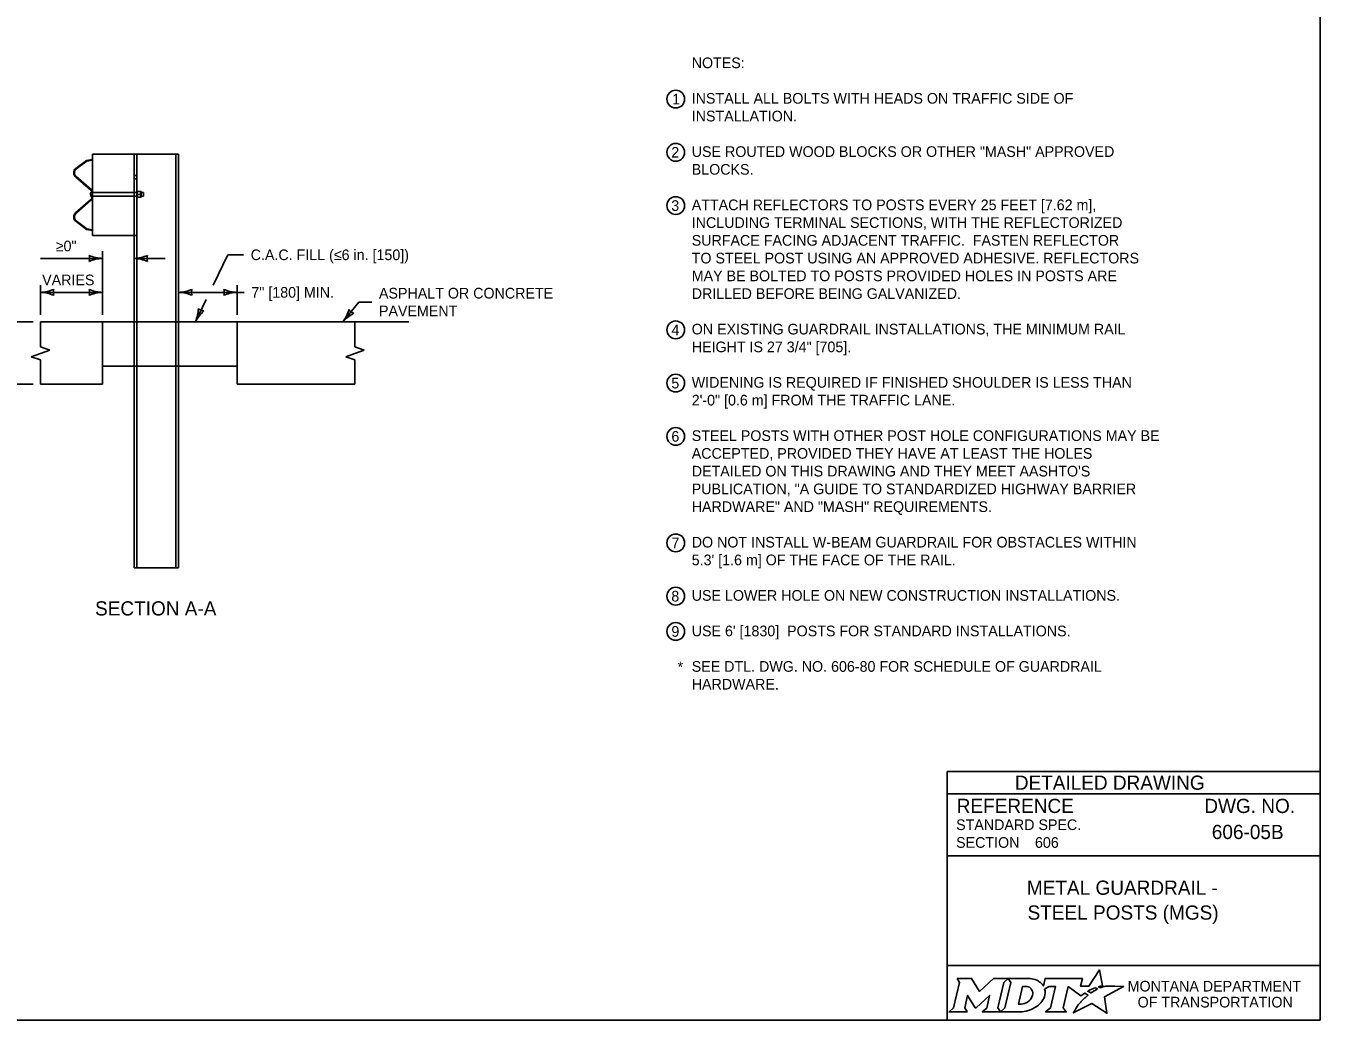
# Model space of a CAD drawing. Extents: x 49991.4 to 50021, y 49987.6 to 50011.4.
# Drawn here: x 50009.46 to 50016.75, y 49987.8 to 49993.4 of the extents above; entities that cross this region are included whole.
import ezdxf

# ---------------------------------------------------------------- set-up
doc = ezdxf.new("R2010")
doc.units = 0
for name, color, linetype in [('Default', 7, 'Continuous'), ('Level 1', 7, 'Continuous'), ('Level 2', 7, 'Continuous'), ('Level 3', 7, 'Continuous'), ('Level 4', 7, 'Continuous'), ('Level 5', 7, 'Continuous'), ('Level 6', 7, 'Continuous')]:
    doc.layers.add(name, color=color, linetype=linetype)

msp = doc.modelspace()

# ---------------------------------------------------------------- linework, layer by layer
at = {"layer": 'Default'}
for points in [[(50014.7056, 49988.0338), (50014.7197, 49988.0104), (50014.6862, 49987.8671), (50014.6605, 49987.8446), (50014.7621, 49987.8446), (50014.7486, 49987.8674), (50014.7648, 49987.9375), (50014.8085, 49987.8685), (50014.8138, 49987.8685), (50014.8889, 49987.938), (50014.8725, 49987.8669), (50014.8478, 49987.8449), (50014.9494, 49987.8449), (50014.9356, 49987.8682), (50014.9688, 49988.0106)], [(50014.9688, 49988.0106), (50014.9941, 49988.0338), (50014.9117, 49988.0338), (50014.8321, 49987.9608), (50014.7876, 49988.0335), (50014.7056, 49988.0338)], [(50015.1077, 49988.0338), (50014.9941, 49988.0338), (50015.0088, 49988.0109), (50014.9749, 49987.8671), (50014.9494, 49987.8449), (50015.06, 49987.8449)], [(50015.5126, 49987.9811), (50015.5023, 49987.9867), (50015.5139, 49987.9895), (50015.5255, 49987.9915), (50015.5081, 49988.0816), (50015.4486, 49987.9903), (50015.4013, 49987.9896), (50015.4116, 49988.0337), (50015.2024, 49988.0338), (50015.1923, 49987.9913), (50015.1865, 49987.9996)], [(50015.1317, 49987.9471), (50015.1305, 49987.939), (50015.1273, 49987.9297), (50015.1231, 49987.9215), (50015.1175, 49987.914), (50015.111, 49987.9071), (50015.1031, 49987.9008), (50015.0948, 49987.8961), (50015.0857, 49987.8922), (50015.0766, 49987.8899), (50015.0674, 49987.889), (50015.0515, 49987.889), (50015.0751, 49987.989), (50015.0911, 49987.989), (50015.0987, 49987.9884), (50015.1063, 49987.9865), (50015.1129, 49987.9835), (50015.119, 49987.9793), (50015.1238, 49987.9743), (50015.1275, 49987.9683), (50015.1302, 49987.9621), (50015.1318, 49987.9547), (50015.1318, 49987.9517), (50015.1317, 49987.9471)], [(50015.1991, 49987.9747), (50015.2237, 49987.9878), (50015.2606, 49987.9878), (50015.232, 49987.8673), (50015.2045, 49987.8446), (50015.3207, 49987.8446), (50015.3037, 49987.8675), (50015.3319, 49987.9877), (50015.4032, 49987.936), (50015.4243, 49987.9511), (50015.444, 49987.9402)], [(50015.3882, 49987.8843), (50015.3729, 49987.8599), (50015.3682, 49987.8524), (50015.3624, 49987.8438), (50015.3601, 49987.8395), (50015.4654, 49987.8926), (50015.5493, 49987.8375), (50015.5362, 49987.9302), (50015.6431, 49987.9886), (50015.5938, 49987.9894), (50015.5637, 49987.9898), (50015.5429, 49987.9901), (50015.5361, 49987.9886), (50015.5312, 49987.9874), (50015.5228, 49987.9851), (50015.5126, 49987.9811)], [(50015.4622, 49987.9535), (50015.4598, 49987.9518), (50015.4415, 49987.9614), (50015.4518, 49987.9671), (50015.4559, 49987.9693), (50015.4645, 49987.9733), (50015.4702, 49987.9759), (50015.4781, 49987.9789), (50015.4854, 49987.9816), (50015.4972, 49987.9742), (50015.4932, 49987.9721), (50015.4886, 49987.9696), (50015.4844, 49987.9674), (50015.4794, 49987.9645), (50015.4775, 49987.9634), (50015.4748, 49987.9618), (50015.4723, 49987.9604), (50015.47, 49987.9588), (50015.4674, 49987.957), (50015.4647, 49987.9552), (50015.4622, 49987.9535)], [(50015.1057, 49987.8522), (50015.1141, 49987.8548), (50015.1271, 49987.8602), (50015.1475, 49987.8712)], [(50015.4021, 49987.9004), (50015.4021, 49987.9004)]]:
    msp.add_lwpolyline(points, dxfattribs=at)
for centre, radius, start, end in [((50015.1308, 49987.9554), 0.0709, 339.53292, 15.85821), ((50015.0868, 49987.9727), 0.1183, 300.91025, 339.13831)]:
    msp.add_arc(centre, radius, start, end, dxfattribs=at)
for centre, major_axis, ratio, start_param, end_param in [((50015.1056, 49987.9864), (0.0834, -0.0037), 0.568097, 0.61298, 1.570796), ((50015.1612, 49987.9937), (0.0361, -0.0295), 0.469099, 1.225588, 1.570796), ((50015.4329, 49987.9305), (-0.0112, -0.0097), 0.021651, 3.157348, 6.283185), ((50015.3952, 49987.8923), (-0.00694, -0.00806), 0.008222, 0, 3.137361), ((50015.4119, 49987.9106), (-0.0098, -0.0102), 0.016458, 3.141593, 6.279097), ((50015.0603, 49987.9932), (0, 0.1484), 0.987302, 3.139398, 3.456847)]:
    msp.add_ellipse(centre, major_axis=major_axis, ratio=ratio, start_param=start_param, end_param=end_param, dxfattribs=at)
at = {"layer": 'Level 1'}
for p, q in [((50009.8373, 49992.6765), (50010.1496, 49992.6766)), ((50009.8373, 49992.2175), (50009.8373, 49992.6765)), ((50010.0874, 49992.6765), (50010.0874, 49991.7316)), ((50010.2433, 49992.6766), (50010.1496, 49992.6766)), ((50010.2433, 49992.6766), (50010.3216, 49992.6766)), ((50010.3057, 49992.6766), (50010.3057, 49991.7316)), ((50010.3216, 49992.6766), (50010.3216, 49991.7316)), ((50009.8033, 49992.6409), (50009.7436, 49992.5962)), ((50009.8049, 49992.6373), (50009.7459, 49992.5931)), ((50009.8373, 49992.647), (50009.8033, 49992.6409)), ((50009.8373, 49992.6429), (50009.8049, 49992.6373)), ((50009.7419, 49992.5484), (50009.827, 49992.4743)), ((50009.7444, 49992.5513), (50009.8295, 49992.4772)), ((50010.0874, 49992.4704), (50010.0893, 49992.4704)), ((50010.0893, 49992.4704), (50010.0893, 49992.4293)), ((50010.0894, 49992.4665), (50010.1109, 49992.4665)), ((50010.1109, 49992.4335), (50010.1109, 49992.4665)), ((50010.124, 49992.4596), (50010.1109, 49992.4596)), ((50010.124, 49992.4596), (50010.124, 49992.4402)), ((50009.7419, 49992.346), (50009.8267, 49992.4199)), ((50009.7444, 49992.3431), (50009.8309, 49992.4184)), ((50009.8354, 49992.4501), (50009.8256, 49992.4501)), ((50010.0874, 49992.4293), (50010.0893, 49992.4293)), ((50010.0893, 49992.4501), (50010.1109, 49992.4501)), ((50010.0894, 49992.4335), (50010.1109, 49992.4335)), ((50010.124, 49992.4402), (50010.1109, 49992.4402)), ((50009.8033, 49992.253), (50009.7436, 49992.2982)), ((50009.8049, 49992.2567), (50009.7459, 49992.3013)), ((50009.8373, 49992.247), (50009.8033, 49992.253)), ((50009.8373, 49992.251), (50009.8049, 49992.2567)), ((50009.8373, 49992.2175), (50010.0874, 49992.2175)), ((50010.0715, 49991.7316), (50010.0715, 49992.2175)), ((50009.5438, 49991.7316), (50010.0715, 49991.7316)), ((50009.8938, 49991.3816), (50009.8938, 49991.7316)), ((50010.3216, 49991.7316), (50011.6178, 49991.7316)), ((50010.652, 49991.7316), (50010.652, 49991.3816)), ((50010.0715, 49991.4829), (50009.8938, 49991.4829)), ((50010.3216, 49991.4829), (50010.652, 49991.4829)), ((50009.5438, 49991.3816), (50009.8938, 49991.3816)), ((50010.652, 49991.3816), (50011.3152, 49991.3816))]:
    msp.add_line(p, q, dxfattribs=at)
for points in [[(49999.3835, 49998.9992), (50016.7501, 49998.9992), (50016.7501, 49987.7988), (49999.3835, 49987.7988)], [(50009.8938, 49991.7316), (50010.652, 49991.7316), (50010.652, 49991.4829), (50009.8938, 49991.4829)]]:
    msp.add_lwpolyline(points, close=True, dxfattribs=at)
for centre, radius, start, end in [((50009.7621, 49992.5716), 0.0308, 126.89692, 228.93931), ((50009.7621, 49992.5716), 0.0269, 126.89692, 228.93931), ((50009.8068, 49992.4512), 0.0306, 5.90227, 48.93931), ((50009.8068, 49992.4512), 0.0345, 28.10432, 48.93931), ((50009.8068, 49992.4432), 0.0306, 310.4718, 354.09773), ((50009.8068, 49992.4432), 0.0345, 314.1015, 331.89568), ((50009.7621, 49992.3228), 0.0308, 131.06069, 233.10308), ((50009.7621, 49992.3228), 0.0269, 131.06069, 233.10308)]:
    msp.add_arc(centre, radius, start, end, dxfattribs=at)
for centre, major_axis, ratio, start_param, end_param in [((50009.8353, 49992.4498), (0, 0.0146), 0.663267, 0.091019, 3.253139), ((50010.1024, 49992.4583), (0.00829, 0.00104), 0.990733, 4.587776, 7.59993), ((50010.1024, 49992.4418), (-0.00829, -0.00104), 0.990733, 1.547621, 4.582997)]:
    msp.add_ellipse(centre, major_axis=major_axis, ratio=ratio, start_param=start_param, end_param=end_param, dxfattribs=at)
at = {"layer": 'Level 2'}
for centre in [(50013.1216, 49992.9868), (50013.1216, 49992.6868), (50013.1216, 49992.3868), (50013.1216, 49991.6868), (50013.1216, 49991.3868), (50013.1216, 49991.0868), (50013.1216, 49990.4868), (50013.1216, 49990.1868), (50013.1216, 49989.9882)]:
    msp.add_circle(centre, 0.05, dxfattribs=at)
at = {"layer": 'Level 3'}
for p, q in [((50009.8938, 49991.7716), (50009.8938, 49992.1293)), ((50010.5161, 49991.9381), (50010.5987, 49992.1096)), ((50010.5987, 49992.1096), (50010.6881, 49992.1096)), ((50009.5438, 49992.0893), (50009.8938, 49992.0893)), ((50010.0715, 49992.0893), (50010.2465, 49992.0893)), ((50009.5438, 49991.7716), (50009.5438, 49991.9381)), ((50009.5438, 49991.8981), (50009.8938, 49991.8981)), ((50010.3216, 49991.8981), (50010.4969, 49991.8981)), ((50010.4969, 49991.8981), (50010.692, 49991.8981)), ((50010.652, 49991.7716), (50010.652, 49991.9381)), ((50010.4168, 49991.7316), (50010.4776, 49991.8581)), ((50011.3365, 49991.8434), (50011.2475, 49991.7316)), ((50011.4104, 49991.8434), (50011.3365, 49991.8434)), ((50009.1538, 49991.7316), (50009.5038, 49991.7316)), ((50009.1538, 49991.3816), (50009.5038, 49991.3816))]:
    msp.add_line(p, q, dxfattribs=at)
for centre, radius, start, end in [((50009.903, 49992.3114), 0.2223, 247.45601, 267.63952), ((50009.7656, 49992.0893), 0.0548, 342.13882, 17.86118), ((50010.06, 49992.322), 0.233, 272.82731, 292.07716), ((50010.1997, 49992.0893), 0.0548, 162.13882, 197.86118), ((50009.9053, 49991.8566), 0.233, 92.82731, 112.07716), ((50010.0623, 49991.8671), 0.2223, 67.45601, 87.63952), ((50009.5323, 49992.1308), 0.233, 272.82731, 292.07716), ((50009.5347, 49991.676), 0.2223, 67.45601, 87.63952), ((50009.672, 49991.8981), 0.0548, 162.13882, 197.86118), ((50009.903, 49992.1202), 0.2223, 247.45601, 267.63952), ((50009.7656, 49991.8981), 0.0548, 342.13882, 17.86118), ((50009.9053, 49991.6654), 0.233, 92.82731, 112.07716), ((50010.3101, 49992.1308), 0.233, 272.82731, 292.07716), ((50010.3124, 49991.676), 0.2223, 67.45601, 87.63952), ((50010.4498, 49991.8981), 0.0548, 162.13882, 197.86118), ((50010.6612, 49992.1202), 0.2223, 247.45601, 267.63952), ((50010.5238, 49991.8981), 0.0548, 342.13882, 17.86118), ((50010.6635, 49991.6654), 0.233, 92.82731, 112.07716), ((50010.201, 49991.8196), 0.233, 337.82731, 357.07716), ((50010.471, 49991.8478), 0.0548, 227.13882, 262.86118), ((50011.0582, 49991.8676), 0.233, 324.30303, 343.55288), ((50011.3273, 49991.8319), 0.0548, 213.61454, 249.3369), ((50010.6142, 49991.6295), 0.2223, 132.45601, 152.63952), ((50011.4155, 49991.5861), 0.2223, 118.93173, 139.11524)]:
    msp.add_arc(centre, radius, start, end, dxfattribs=at)
at = {"layer": 'Level 4'}
for p, q in [((50010.0715, 49992.6765), (50010.0715, 49992.2175)), ((50010.0874, 49992.5568), (50010.0715, 49992.5568)), ((50010.0874, 49992.5374), (50010.0715, 49992.5374)), ((50010.0874, 49992.4596), (50009.8373, 49992.4596)), ((50010.0874, 49992.4402), (50009.8373, 49992.4402)), ((50010.0715, 49991.7316), (50010.0715, 49990.3468)), ((50010.0874, 49991.7316), (50010.0874, 49990.3468)), ((50010.3057, 49990.3468), (50010.3057, 49991.7316)), ((50010.3216, 49990.3468), (50010.3216, 49991.7316)), ((50010.0715, 49990.3468), (50010.3216, 49990.3468)), ((50014.6501, 49989.1988), (50014.6501, 49987.7988)), ((50016.7501, 49989.1988), (50014.6501, 49989.1988)), ((50016.7501, 49989.0738), (50014.6501, 49989.0738)), ((50016.7501, 49988.7238), (50014.6501, 49988.7238)), ((50016.7501, 49988.1057), (50014.6501, 49988.1057))]:
    msp.add_line(p, q, dxfattribs=at)
at = {"layer": 'Level 5'}
for p, q in [((50016.3862, 49988.8587), (50016.3862, 49988.8587)), ((50015.1444, 49988.7993), (50015.1444, 49988.7993)), ((50015.7001, 49988.4747), (50015.7001, 49988.4747))]:
    msp.add_line(p, q, dxfattribs=at)
at = {"layer": 'Level 6'}
for p, q in [((50009.5438, 49991.7316), (50009.5438, 49991.5913)), ((50011.3152, 49991.7316), (50011.3152, 49991.5913)), ((50009.5962, 49991.5728), (50009.5438, 49991.5913)), ((50011.3676, 49991.5728), (50011.3152, 49991.5913)), ((50009.5438, 49991.5542), (50009.4915, 49991.5357)), ((50009.5438, 49991.5171), (50009.4915, 49991.5357)), ((50009.5962, 49991.5728), (50009.5438, 49991.5542)), ((50009.5438, 49991.5171), (50009.5438, 49991.3816)), ((50011.3152, 49991.5542), (50011.2629, 49991.5357)), ((50011.3152, 49991.5171), (50011.2629, 49991.5357)), ((50011.3676, 49991.5728), (50011.3152, 49991.5542)), ((50011.3152, 49991.5171), (50011.3152, 49991.3816))]:
    msp.add_line(p, q, dxfattribs=at)

# ---------------------------------------------------------------- texts
at = {"layer": 'Default'}
for s, p in [('MONTANA DEPARTMENT', (50015.6663, 49987.96)), ('OF TRANSPORTATION', (50015.7225, 49987.87))]:
    msp.add_text(s, height=0.06, rotation=360, dxfattribs=at).set_placement(p)
at = {"layer": 'Level 2'}
for s, height, p in [('NOTES:', 0.06, (50013.2116, 49993.1609)), ('1', 0.06, (50013.1018, 49992.9568)), ('INSTALL ALL BOLTS WITH HEADS ON TRAFFIC SIDE OF ', 0.06, (50013.2116, 49992.9609)), ('INSTALLATION.', 0.06, (50013.2116, 49992.8609)), ('2', 0.06, (50013.0964, 49992.6568)), ('USE ROUTED WOOD BLOCKS OR OTHER "MASH" APPROVED ', 0.06, (50013.2116, 49992.6609)), ('BLOCKS.', 0.06, (50013.2116, 49992.5609)), ('3', 0.06, (50013.0964, 49992.3568)), ('ATTACH REFLECTORS TO POSTS EVERY 25 FEET [7.62 m], ', 0.06, (50013.2116, 49992.3609)), ('INCLUDING TERMINAL SECTIONS, WITH THE REFLECTORIZED ', 0.06, (50013.2116, 49992.2609)), ('≥0"', 0.06, (50009.6302, 49992.1293)), ('SURFACE FACING ADJACENT TRAFFIC.  FASTEN REFLECTOR ', 0.06, (50013.2116, 49992.1609)), ('C.A.C. FILL (≤6 in. [150])', 0.06, (50010.7281, 49992.0796)), ('TO STEEL POST USING AN APPROVED ADHESIVE. REFLECTORS ', 0.06, (50013.2116, 49992.0609)), ('MAY BE BOLTED TO POSTS PROVIDED HOLES IN POSTS ARE ', 0.06, (50013.2116, 49991.9609)), ('VARIES', 0.06, (50009.5538, 49991.9381)), ('7" [180] MIN.', 0.06, (50010.732, 49991.8681)), ('ASPHALT OR CONCRETE', 0.06, (50011.4504, 49991.8634)), ('DRILLED BEFORE BEING GALVANIZED.', 0.06, (50013.2116, 49991.8609)), ('PAVEMENT', 0.06, (50011.4504, 49991.7634)), ('4', 0.06, (50013.0976, 49991.6568)), ('ON EXISTING GUARDRAIL INSTALLATIONS, THE MINIMUM RAIL ', 0.06, (50013.2116, 49991.6609)), ('HEIGHT IS 27 3/4" [705].', 0.06, (50013.2116, 49991.5609)), ('5', 0.06, (50013.0967, 49991.3568)), ('WIDENING IS REQUIRED IF FINISHED SHOULDER IS LESS THAN ', 0.06, (50013.2116, 49991.3609)), ('2\'-0" [0.6 m] FROM THE TRAFFIC LANE.', 0.06, (50013.2116, 49991.2609)), ('6', 0.06, (50013.0971, 49991.0568)), ('STEEL POSTS WITH OTHER POST HOLE CONFIGURATIONS MAY BE ', 0.06, (50013.2116, 49991.0609)), ('ACCEPTED, PROVIDED THEY HAVE AT LEAST THE HOLES ', 0.06, (50013.2116, 49990.9609)), ("DETAILED ON THIS DRAWING AND THEY MEET AASHTO'S ", 0.06, (50013.2116, 49990.8609)), ('PUBLICATION, "A GUIDE TO STANDARDIZED HIGHWAY BARRIER ', 0.06, (50013.2116, 49990.7609)), ('HARDWARE" AND "MASH" REQUIREMENTS.', 0.06, (50013.2116, 49990.6609)), ('7', 0.06, (50013.0978, 49990.4568)), ('DO NOT INSTALL W-BEAM GUARDRAIL FOR OBSTACLES WITHIN ', 0.06, (50013.2116, 49990.4609)), ("5.3' [1.6 m] OF THE FACE OF THE RAIL.", 0.06, (50013.2116, 49990.3609)), ('8', 0.06, (50013.0966, 49990.1568)), ('USE LOWER HOLE ON NEW CONSTRUCTION INSTALLATIONS.', 0.06, (50013.2116, 49990.1609)), ('SECTION A-A', 0.08, (50009.8516, 49990.0779)), ('9', 0.06, (50013.0971, 49989.9582)), ("USE 6' [1830]  POSTS FOR STANDARD INSTALLATIONS.", 0.06, (50013.2116, 49989.9609)), ('*', 0.06, (50013.1318, 49989.7586)), ('SEE DTL. DWG. NO. 606-80 FOR SCHEDULE OF GUARDRAIL ', 0.06, (50013.2116, 49989.7609)), ('HARDWARE.', 0.06, (50013.2116, 49989.6609)), ('606-05B', 0.08, (50016.1402, 49988.8187)), ('606', 0.06, (50015.1444, 49988.7693)), ('METAL GUARDRAIL -', 0.08, (50015.0988, 49988.5047)), ('STEEL POSTS (MGS)', 0.08, (50015.1026, 49988.3647))]:
    msp.add_text(s, height=height, dxfattribs=at).set_placement(p)
at = {"layer": 'Level 4'}
for s, height, p in [('DETAILED DRAWING', 0.0799, (50015.0311, 49989.0963)), ('REFERENCE', 0.08, (50014.7037, 49988.9654)), ('DWG. NO.', 0.08, (50016.0979, 49988.9654)), ('STANDARD SPEC.', 0.06, (50014.7004, 49988.8694)), ('SECTION', 0.06, (50014.7004, 49988.7694))]:
    msp.add_text(s, height=height, dxfattribs=at).set_placement(p)

doc.saveas('drawing.dxf')
